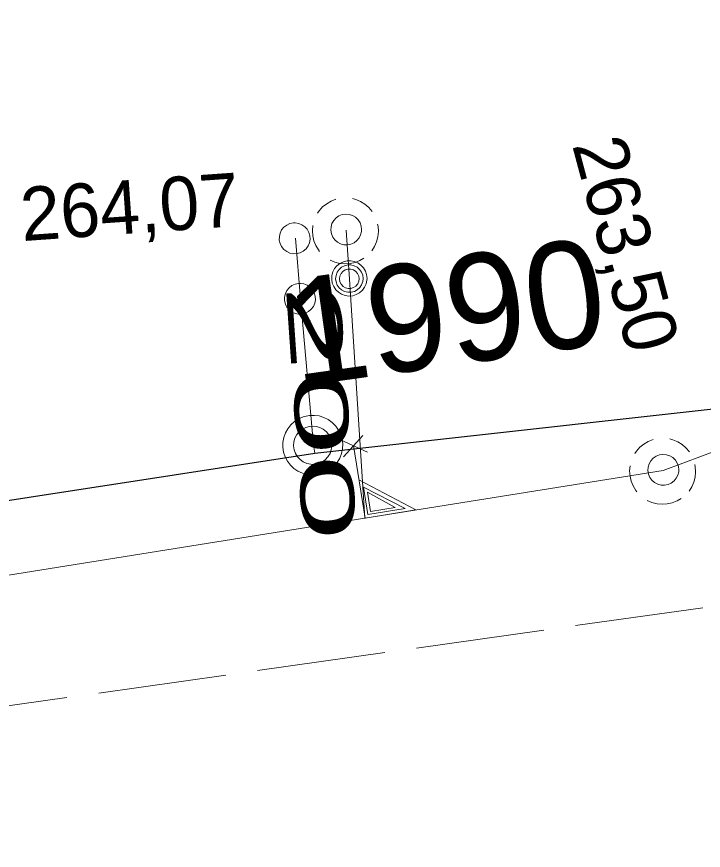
# Model space of a CAD drawing. Extents: x -732096 to -731933, y -1048703 to -1047964.
# Drawn here: x -732049.66 to -732039.39, y -1048253.76 to -1048241.31 of the extents above; entities that cross this region are included whole.
import ezdxf

# ---------------------------------------------------------------- set-up
doc = ezdxf.new("R2010")
doc.units = 0
doc.header["$LTSCALE"] = 0.32
doc.linetypes.add('LONG_DASHED', pattern=[7.5, 6, -1.5])
doc.layers.add('1', color=7, linetype='Continuous')
for name, color, linetype, lineweight in [('18', 7, 'Continuous', 13), ('20', 7, 'Continuous', 13), ('49', 7, 'Continuous', 13), ('8', 7, 'Continuous', 13)]:
    doc.layers.add(name, color=color, linetype=linetype, lineweight=lineweight)

msp = doc.modelspace()

# ---------------------------------------------------------------- linework, layer by layer
at = {"layer": '18'}
for p, q in [((-732044.481, -1048247.564), (-732044.77, -1048247.883)), ((-732044.814, -1048247.63), (-732044.409, -1048247.813))]:
    msp.add_line(p, q, dxfattribs=at)
for points in [[(-732044.883, -1048244.037), (-732044.954, -1048244.065), (-732045.021, -1048244.104), (-732045.081, -1048244.152), (-732045.132, -1048244.209), (-732045.156, -1048244.243)], [(-732044.342, -1048244.22), (-732044.392, -1048244.162), (-732044.45, -1048244.112), (-732044.515, -1048244.071), (-732044.586, -1048244.042), (-732044.635, -1048244.028)], [(-732045.228, -1048244.429), (-732045.233, -1048244.506), (-732045.228, -1048244.583), (-732045.212, -1048244.658), (-732045.183, -1048244.729), (-732045.142, -1048244.795), (-732045.127, -1048244.817)], [(-732044.347, -1048244.806), (-732044.306, -1048244.741), (-732044.275, -1048244.671), (-732044.255, -1048244.596), (-732044.248, -1048244.52), (-732044.253, -1048244.443), (-732044.259, -1048244.408)], [(-732044.97, -1048244.946), (-732044.9, -1048244.977), (-732044.825, -1048244.996), (-732044.749, -1048245.003), (-732044.672, -1048244.998), (-732044.597, -1048244.981), (-732044.525, -1048244.953), (-732044.465, -1048244.918)], [(-732040.142, -1048247.627), (-732040.213, -1048247.655), (-732040.279, -1048247.694), (-732040.34, -1048247.742), (-732040.391, -1048247.799), (-732040.414, -1048247.833)], [(-732039.6, -1048247.81), (-732039.651, -1048247.752), (-732039.708, -1048247.702), (-732039.774, -1048247.661), (-732039.845, -1048247.632), (-732039.894, -1048247.618)], [(-732044.62, -1048247.717), (-732044.447, -1048248.799), (-732043.686, -1048248.677), (-732044.538, -1048248.228)], [(-732040.487, -1048248.019), (-732040.492, -1048248.096), (-732040.487, -1048248.173), (-732040.47, -1048248.248), (-732040.441, -1048248.319), (-732040.401, -1048248.385), (-732040.386, -1048248.407)], [(-732039.605, -1048248.396), (-732039.565, -1048248.331), (-732039.534, -1048248.261), (-732039.514, -1048248.186), (-732039.507, -1048248.11), (-732039.512, -1048248.033), (-732039.517, -1048247.998)], [(-732044.469, -1048248.337), (-732044.404, -1048248.748), (-732043.846, -1048248.658), (-732044.469, -1048248.336)], [(-732044.41, -1048248.412), (-732044.364, -1048248.7), (-732043.997, -1048248.641), (-732044.411, -1048248.413)], [(-732040.228, -1048248.536), (-732040.159, -1048248.567), (-732040.083, -1048248.586), (-732040.007, -1048248.593), (-732039.931, -1048248.588), (-732039.855, -1048248.571), (-732039.784, -1048248.543), (-732039.723, -1048248.508)]]:
    msp.add_lwpolyline(points, dxfattribs=at)
for points in [[(-732044.499, -1048244.489), (-732044.505, -1048244.437), (-732044.522, -1048244.387), (-732044.551, -1048244.343), (-732044.589, -1048244.306), (-732044.634, -1048244.279), (-732044.684, -1048244.263), (-732044.736, -1048244.258), (-732044.788, -1048244.265), (-732044.837, -1048244.284), (-732044.88, -1048244.314), (-732044.916, -1048244.353), (-732044.942, -1048244.398), (-732044.956, -1048244.449), (-732044.96, -1048244.501), (-732044.951, -1048244.553), (-732044.931, -1048244.601), (-732044.901, -1048244.644), (-732044.861, -1048244.679), (-732044.815, -1048244.703), (-732044.764, -1048244.717), (-732044.712, -1048244.719), (-732044.66, -1048244.709), (-732044.612, -1048244.687), (-732044.57, -1048244.655), (-732044.537, -1048244.615), (-732044.513, -1048244.568), (-732044.5, -1048244.517)], [(-732044.418, -1048245.219), (-732044.424, -1048245.163), (-732044.441, -1048245.11), (-732044.47, -1048245.061), (-732044.508, -1048245.02), (-732044.554, -1048244.988), (-732044.606, -1048244.966), (-732044.661, -1048244.955), (-732044.717, -1048244.957), (-732044.772, -1048244.97), (-732044.823, -1048244.995), (-732044.867, -1048245.03), (-732044.903, -1048245.073), (-732044.928, -1048245.123), (-732044.943, -1048245.178), (-732044.946, -1048245.234), (-732044.937, -1048245.289), (-732044.916, -1048245.342), (-732044.885, -1048245.388), (-732044.845, -1048245.427), (-732044.797, -1048245.457), (-732044.744, -1048245.476), (-732044.688, -1048245.483), (-732044.632, -1048245.479), (-732044.578, -1048245.462), (-732044.529, -1048245.435), (-732044.487, -1048245.397), (-732044.454, -1048245.352), (-732044.431, -1048245.301), (-732044.419, -1048245.246)], [(-732044.477, -1048245.222), (-732044.483, -1048245.173), (-732044.501, -1048245.127), (-732044.529, -1048245.086), (-732044.566, -1048245.053), (-732044.61, -1048245.031), (-732044.658, -1048245.019), (-732044.707, -1048245.019), (-732044.755, -1048245.031), (-732044.799, -1048245.054), (-732044.836, -1048245.087), (-732044.864, -1048245.128), (-732044.881, -1048245.175), (-732044.887, -1048245.224), (-732044.88, -1048245.273), (-732044.862, -1048245.319), (-732044.834, -1048245.359), (-732044.797, -1048245.392), (-732044.753, -1048245.414), (-732044.704, -1048245.426), (-732044.655, -1048245.425), (-732044.607, -1048245.413), (-732044.564, -1048245.389), (-732044.527, -1048245.356), (-732044.499, -1048245.315), (-732044.483, -1048245.268)], [(-732044.536, -1048245.226), (-732044.542, -1048245.184), (-732044.559, -1048245.146), (-732044.587, -1048245.115), (-732044.622, -1048245.092), (-732044.662, -1048245.081), (-732044.704, -1048245.081), (-732044.744, -1048245.093), (-732044.779, -1048245.116), (-732044.806, -1048245.148), (-732044.823, -1048245.186), (-732044.828, -1048245.227), (-732044.822, -1048245.269), (-732044.804, -1048245.306), (-732044.776, -1048245.338), (-732044.74, -1048245.36), (-732044.7, -1048245.371), (-732044.658, -1048245.37), (-732044.618, -1048245.357), (-732044.584, -1048245.334), (-732044.557, -1048245.301), (-732044.541, -1048245.263)], [(-732039.757, -1048248.079), (-732039.764, -1048248.027), (-732039.781, -1048247.977), (-732039.809, -1048247.933), (-732039.848, -1048247.896), (-732039.892, -1048247.869), (-732039.943, -1048247.853), (-732039.995, -1048247.848), (-732040.046, -1048247.855), (-732040.095, -1048247.874), (-732040.139, -1048247.904), (-732040.174, -1048247.943), (-732040.201, -1048247.988), (-732040.215, -1048248.039), (-732040.218, -1048248.091), (-732040.21, -1048248.143), (-732040.19, -1048248.191), (-732040.159, -1048248.234), (-732040.12, -1048248.269), (-732040.073, -1048248.293), (-732040.022, -1048248.307), (-732039.97, -1048248.309), (-732039.919, -1048248.299), (-732039.87, -1048248.277), (-732039.828, -1048248.245), (-732039.796, -1048248.205), (-732039.772, -1048248.158), (-732039.759, -1048248.107)]]:
    msp.add_lwpolyline(points, close=True, dxfattribs=at)
at = {"layer": '20'}
msp.add_line((-732039.989, -1048248.09), (-732027.55, -1048243.38), dxfattribs=at)
msp.add_line((-732039.989, -1048248.09), (-732027.55, -1048243.38), dxfattribs=at)
at = {"layer": '20', "linetype": 'LONG_DASHED'}
msp.add_line((-732065.064, -1048253.762), (-732038.07, -1048249.95), dxfattribs=at)
msp.add_line((-732065.064, -1048253.762), (-732038.07, -1048249.95), dxfattribs=at)
at = {"layer": '20'}
msp.add_lwpolyline([(-732064.67, -1048252.033), (-732044.453, -1048248.803), (-732039.989, -1048248.09)], dxfattribs=at)
msp.add_lwpolyline([(-732064.67, -1048252.033), (-732044.453, -1048248.803), (-732039.989, -1048248.09)], dxfattribs=at)
at = {"layer": '49'}
msp.add_lwpolyline([(-732044.73, -1048244.5), (-732044.682, -1048245.232), (-732044.453, -1048248.803)], dxfattribs=at)
msp.add_lwpolyline([(-732044.73, -1048244.5), (-732044.682, -1048245.232), (-732044.453, -1048248.803)], dxfattribs=at)
at = {"layer": '8'}
for p, q in [((-732045.41, -1048245.524), (-732045.489, -1048244.62)), ((-732045.219, -1048247.71), (-732045.41, -1048245.524)), ((-732045.199, -1048247.83), (-732045.219, -1048247.71))]:
    msp.add_line(p, q, dxfattribs=at)
at = {"layer": '8', "lineweight": 25}
msp.add_lwpolyline([(-732064.384, -1048250.784), (-732045.199, -1048247.83), (-732034.949, -1048246.69), (-732033.82, -1048241.31)], dxfattribs=at)
at = {"layer": '8'}
for points in [[(-732045.519, -1048244.39), (-732045.57, -1048244.401), (-732045.619, -1048244.423), (-732045.66, -1048244.455), (-732045.694, -1048244.496), (-732045.717, -1048244.543), (-732045.728, -1048244.594), (-732045.729, -1048244.646), (-732045.717, -1048244.698), (-732045.694, -1048244.745), (-732045.66, -1048244.786), (-732045.618, -1048244.818), (-732045.571, -1048244.84), (-732045.519, -1048244.85), (-732045.467, -1048244.848), (-732045.416, -1048244.836), (-732045.37, -1048244.811), (-732045.33, -1048244.777), (-732045.298, -1048244.734), (-732045.278, -1048244.686), (-732045.269, -1048244.634), (-732045.271, -1048244.582), (-732045.286, -1048244.532), (-732045.312, -1048244.486), (-732045.348, -1048244.447), (-732045.39, -1048244.417), (-732045.439, -1048244.397), (-732045.491, -1048244.39)], [(-732045.44, -1048245.294), (-732045.491, -1048245.305), (-732045.54, -1048245.327), (-732045.581, -1048245.359), (-732045.615, -1048245.4), (-732045.638, -1048245.447), (-732045.649, -1048245.498), (-732045.65, -1048245.551), (-732045.638, -1048245.602), (-732045.615, -1048245.649), (-732045.581, -1048245.69), (-732045.539, -1048245.722), (-732045.492, -1048245.744), (-732045.44, -1048245.754), (-732045.388, -1048245.752), (-732045.337, -1048245.74), (-732045.291, -1048245.715), (-732045.251, -1048245.681), (-732045.219, -1048245.638), (-732045.199, -1048245.59), (-732045.19, -1048245.538), (-732045.192, -1048245.486), (-732045.207, -1048245.436), (-732045.233, -1048245.39), (-732045.269, -1048245.351), (-732045.311, -1048245.321), (-732045.36, -1048245.301), (-732045.412, -1048245.294)], [(-732045.302, -1048247.27), (-732045.373, -1048247.288), (-732045.44, -1048247.318), (-732045.502, -1048247.357), (-732045.555, -1048247.407), (-732045.602, -1048247.464), (-732045.637, -1048247.528), (-732045.661, -1048247.597), (-732045.674, -1048247.669), (-732045.675, -1048247.742), (-732045.664, -1048247.815), (-732045.641, -1048247.884), (-732045.607, -1048247.95), (-732045.564, -1048248.007), (-732045.511, -1048248.058), (-732045.45, -1048248.1), (-732045.384, -1048248.13), (-732045.313, -1048248.15), (-732045.241, -1048248.158), (-732045.167, -1048248.154), (-732045.096, -1048248.138), (-732045.028, -1048248.111), (-732044.966, -1048248.073), (-732044.91, -1048248.025), (-732044.864, -1048247.969), (-732044.826, -1048247.906), (-732044.8, -1048247.837), (-732044.785, -1048247.766), (-732044.782, -1048247.692), (-732044.791, -1048247.62), (-732044.812, -1048247.549), (-732044.844, -1048247.484), (-732044.886, -1048247.424), (-732044.938, -1048247.372), (-732044.997, -1048247.329), (-732045.063, -1048247.296), (-732045.132, -1048247.274), (-732045.205, -1048247.265), (-732045.278, -1048247.267)], [(-732045.276, -1048247.429), (-732045.332, -1048247.445), (-732045.384, -1048247.472), (-732045.43, -1048247.508), (-732045.467, -1048247.553), (-732045.495, -1048247.605), (-732045.511, -1048247.661), (-732045.515, -1048247.719), (-732045.508, -1048247.778), (-732045.488, -1048247.833), (-732045.458, -1048247.883), (-732045.418, -1048247.926), (-732045.371, -1048247.96), (-732045.317, -1048247.983), (-732045.259, -1048247.996), (-732045.202, -1048247.997), (-732045.144, -1048247.985), (-732045.09, -1048247.962), (-732045.042, -1048247.928), (-732045.002, -1048247.885), (-732044.971, -1048247.836), (-732044.952, -1048247.781), (-732044.943, -1048247.722), (-732044.947, -1048247.664), (-732044.962, -1048247.608), (-732044.988, -1048247.556), (-732045.025, -1048247.51), (-732045.071, -1048247.473), (-732045.122, -1048247.446), (-732045.178, -1048247.43), (-732045.237, -1048247.426)]]:
    msp.add_lwpolyline(points, close=True, dxfattribs=at)

# ---------------------------------------------------------------- texts
at = {"layer": '1'}
for s, height, rotation, p in [('263,50', 0.8, 285, (-732041.355, -1048243.224)), ('264,07', 0.8, 4, (-732049.571, -1048244.663)), ('1990', 1.6, 8, (-732045.483, -1048246.843))]:
    msp.add_text(s, height=height, rotation=rotation, dxfattribs=at).set_placement(p)
at = {"layer": '1', "width": 2.15}
msp.add_text('200 ', height=0.8, rotation=274, dxfattribs=at).set_placement((-732045.633, -1048245.33))

doc.saveas('drawing.dxf')
